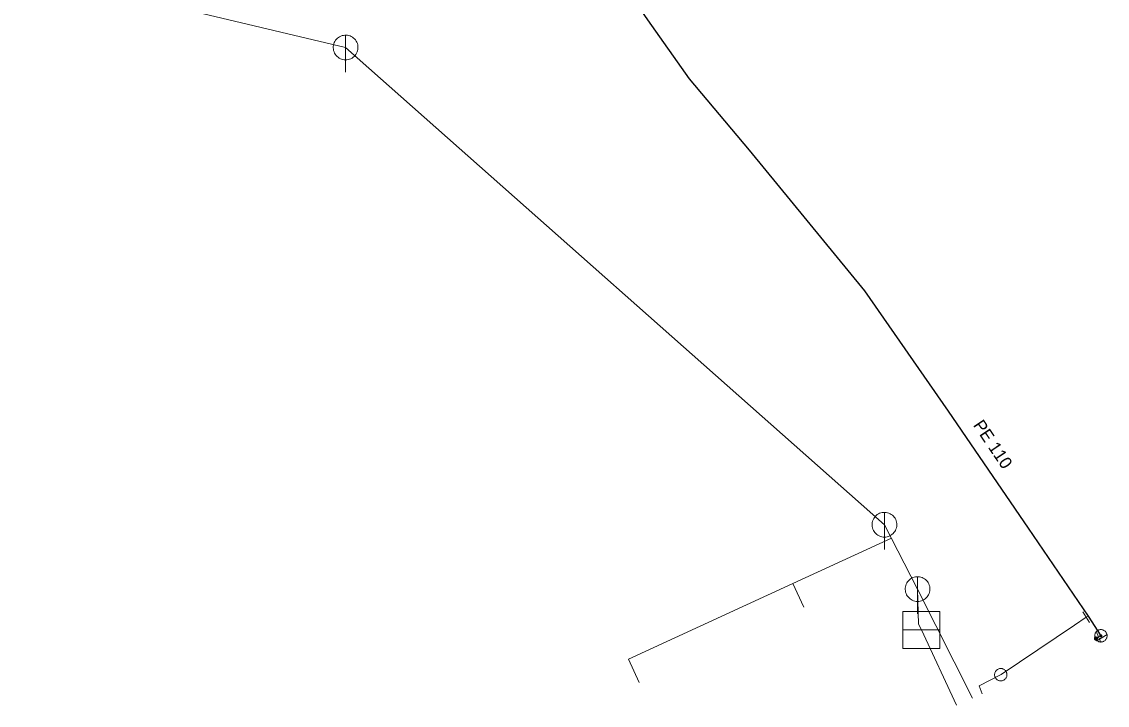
# Model space of a CAD drawing. Extents: x -659250 to -657316, y -997555 to -993684.
# Drawn here: x -658094.3 to -658006.5, y -996520.5 to -996465.3 of the extents above; entities that cross this region are included whole.
import ezdxf

# ---------------------------------------------------------------- set-up
doc = ezdxf.new("R2010")
doc.units = 0
doc.header["$LTSCALE"] = 0.4
doc.layers.add('1', color=7, linetype='Continuous')
for name, color, linetype, lineweight in [('11', 7, 'Continuous', 13), ('13', 7, 'Continuous', 13), ('14', 7, 'Continuous', 25), ('17', 7, 'Continuous', 25), ('22', 7, 'Continuous', 13), ('23', 7, 'Continuous', 13), ('34', 7, 'Continuous', 13), ('47', 7, 'Continuous', 13), ('9', 7, 'Continuous', 13)]:
    doc.layers.add(name, color=color, linetype=linetype, lineweight=lineweight)

msp = doc.modelspace()

# ---------------------------------------------------------------- linework, layer by layer
at = {"layer": '11'}
for p, q in [((-658068.112, -996467.351), (-658094.3, -996461.12)), ((-658024.55, -996505.92), (-658068.112, -996467.351)), ((-658021.87, -996511.12), (-658024.55, -996505.92)), ((-658031.061, -996512.596), (-658031.954, -996510.66)), ((-658017.443, -996519.932), (-658021.87, -996511.12)), ((-658018.721, -996520.515), (-658021.559, -996514.43))]:
    msp.add_line(p, q, dxfattribs=at)
for points in [[(-658044.375, -996518.677), (-658045.245, -996516.787), (-658031.954, -996510.66), (-658023.992, -996507)], [(-658021.559, -996514.43), (-658021.789, -996513.969), (-658021.87, -996511.12)]]:
    msp.add_lwpolyline(points, dxfattribs=at)
at = {"layer": '13'}
for points in [[(-658008.239, -996513.399), (-658009.18, -996514.05), (-658015.12, -996518.02)], [(-658015.12, -996518.02), (-658016.879, -996518.93), (-658016.64, -996519.579)]]:
    msp.add_lwpolyline(points, dxfattribs=at)
at = {"layer": '14', "lineweight": 13}
for p, q in [((-658008.079, -996513.3), (-658008.239, -996513.399)), ((-658007.25, -996514.98), (-658007.449, -996515.12)), ((-658007.05, -996514.899), (-658007.25, -996514.98))]:
    msp.add_line(p, q, dxfattribs=at)
at = {"layer": '17'}
msp.add_line((-658007.05, -996514.899), (-658006.96, -996515.05), dxfattribs=at)
msp.add_lwpolyline([(-658055.539, -996447.693), (-658052.98, -996451.609), (-658043.719, -996465.109), (-658040.35, -996469.87), (-658035.489, -996475.649), (-658026.16, -996487.01), (-658019.39, -996496.739), (-658012.93, -996506.21), (-658008.079, -996513.3), (-658007.05, -996514.899)], dxfattribs=at)
at = {"layer": '22'}
for p, q in [((-658068.112, -996469.351), (-658068.111, -996466.351)), ((-658024.55, -996507.92), (-658024.549, -996504.92)), ((-658021.87, -996513.12), (-658021.869, -996510.12)), ((-658023.059, -996514.43), (-658020.059, -996514.43))]:
    msp.add_line(p, q, dxfattribs=at)
for points in [[(-658067.112, -996467.351), (-658067.117, -996467.242), (-658067.135, -996467.134), (-658067.165, -996467.028), (-658067.205, -996466.927), (-658067.257, -996466.83), (-658067.319, -996466.74), (-658067.391, -996466.657), (-658067.471, -996466.583), (-658067.559, -996466.517), (-658067.653, -996466.462), (-658067.753, -996466.417), (-658067.858, -996466.384), (-658067.965, -996466.362), (-658068.074, -996466.352), (-658068.184, -996466.354), (-658068.292, -996466.368), (-658068.399, -996466.393), (-658068.502, -996466.43), (-658068.6, -996466.479), (-658068.692, -996466.537), (-658068.778, -996466.606), (-658068.855, -996466.683), (-658068.924, -996466.769), (-658068.983, -996466.861), (-658069.031, -996466.959), (-658069.068, -996467.062), (-658069.094, -996467.169), (-658069.108, -996467.277), (-658069.111, -996467.387), (-658069.101, -996467.496), (-658069.08, -996467.603), (-658069.046, -996467.707), (-658069.002, -996467.807), (-658068.947, -996467.902), (-658068.881, -996467.99), (-658068.807, -996468.07), (-658068.724, -996468.142), (-658068.634, -996468.204), (-658068.538, -996468.256), (-658068.436, -996468.297), (-658068.331, -996468.327), (-658068.223, -996468.345), (-658068.113, -996468.351), (-658068.004, -996468.345), (-658067.896, -996468.327), (-658067.791, -996468.298), (-658067.689, -996468.257), (-658067.592, -996468.205), (-658067.502, -996468.143), (-658067.419, -996468.072), (-658067.344, -996467.992), (-658067.279, -996467.904), (-658067.223, -996467.81), (-658067.179, -996467.71), (-658067.145, -996467.606), (-658067.123, -996467.498), (-658067.113, -996467.389)], [(-658023.55, -996505.92), (-658023.555, -996505.811), (-658023.573, -996505.703), (-658023.603, -996505.597), (-658023.643, -996505.496), (-658023.695, -996505.399), (-658023.757, -996505.309), (-658023.829, -996505.226), (-658023.909, -996505.152), (-658023.997, -996505.086), (-658024.091, -996505.031), (-658024.191, -996504.986), (-658024.296, -996504.953), (-658024.403, -996504.931), (-658024.512, -996504.921), (-658024.622, -996504.923), (-658024.73, -996504.937), (-658024.837, -996504.962), (-658024.94, -996504.999), (-658025.038, -996505.048), (-658025.13, -996505.106), (-658025.216, -996505.175), (-658025.293, -996505.252), (-658025.362, -996505.338), (-658025.421, -996505.43), (-658025.469, -996505.528), (-658025.506, -996505.631), (-658025.532, -996505.738), (-658025.546, -996505.846), (-658025.549, -996505.956), (-658025.539, -996506.065), (-658025.518, -996506.172), (-658025.484, -996506.276), (-658025.44, -996506.376), (-658025.385, -996506.471), (-658025.319, -996506.559), (-658025.245, -996506.639), (-658025.162, -996506.711), (-658025.072, -996506.773), (-658024.976, -996506.825), (-658024.874, -996506.866), (-658024.769, -996506.896), (-658024.661, -996506.914), (-658024.551, -996506.92), (-658024.442, -996506.914), (-658024.334, -996506.896), (-658024.229, -996506.867), (-658024.127, -996506.826), (-658024.03, -996506.774), (-658023.94, -996506.712), (-658023.857, -996506.641), (-658023.782, -996506.561), (-658023.717, -996506.473), (-658023.661, -996506.379), (-658023.617, -996506.279), (-658023.583, -996506.175), (-658023.561, -996506.067), (-658023.551, -996505.958)], [(-658020.87, -996511.12), (-658020.875, -996511.011), (-658020.893, -996510.903), (-658020.923, -996510.797), (-658020.963, -996510.696), (-658021.015, -996510.599), (-658021.077, -996510.509), (-658021.149, -996510.426), (-658021.229, -996510.352), (-658021.317, -996510.286), (-658021.411, -996510.231), (-658021.511, -996510.186), (-658021.616, -996510.153), (-658021.723, -996510.131), (-658021.832, -996510.121), (-658021.942, -996510.123), (-658022.05, -996510.137), (-658022.157, -996510.162), (-658022.26, -996510.199), (-658022.358, -996510.248), (-658022.45, -996510.306), (-658022.536, -996510.375), (-658022.613, -996510.452), (-658022.682, -996510.538), (-658022.741, -996510.63), (-658022.789, -996510.728), (-658022.826, -996510.831), (-658022.852, -996510.938), (-658022.866, -996511.046), (-658022.869, -996511.156), (-658022.859, -996511.265), (-658022.838, -996511.372), (-658022.804, -996511.476), (-658022.76, -996511.576), (-658022.705, -996511.671), (-658022.639, -996511.759), (-658022.565, -996511.839), (-658022.482, -996511.911), (-658022.392, -996511.973), (-658022.296, -996512.025), (-658022.194, -996512.066), (-658022.089, -996512.096), (-658021.981, -996512.114), (-658021.871, -996512.12), (-658021.762, -996512.114), (-658021.654, -996512.096), (-658021.549, -996512.067), (-658021.447, -996512.026), (-658021.35, -996511.974), (-658021.26, -996511.912), (-658021.177, -996511.841), (-658021.102, -996511.761), (-658021.037, -996511.673), (-658020.981, -996511.579), (-658020.937, -996511.479), (-658020.903, -996511.375), (-658020.881, -996511.267), (-658020.871, -996511.158)], [(-658023.059, -996512.93), (-658020.059, -996512.93), (-658020.059, -996515.93), (-658023.059, -996515.93)]]:
    msp.add_lwpolyline(points, close=True, dxfattribs=at)
at = {"layer": '23'}
for points in [[(-658014.643, -996518.037), (-658014.646, -996517.984), (-658014.655, -996517.932), (-658014.67, -996517.883), (-658014.689, -996517.834), (-658014.713, -996517.788), (-658014.743, -996517.744), (-658014.776, -996517.704), (-658014.813, -996517.668), (-658014.854, -996517.635), (-658014.898, -996517.607), (-658014.945, -996517.583), (-658014.995, -996517.565), (-658015.045, -996517.552), (-658015.096, -996517.545), (-658015.148, -996517.542), (-658015.202, -996517.546), (-658015.252, -996517.554), (-658015.304, -996517.569), (-658015.351, -996517.587), (-658015.398, -996517.611), (-658015.442, -996517.642), (-658015.482, -996517.675), (-658015.519, -996517.713), (-658015.552, -996517.753), (-658015.579, -996517.797), (-658015.602, -996517.845), (-658015.62, -996517.893), (-658015.633, -996517.944), (-658015.64, -996517.996), (-658015.643, -996518.048), (-658015.64, -996518.1), (-658015.631, -996518.152), (-658015.617, -996518.203), (-658015.598, -996518.251), (-658015.573, -996518.296), (-658015.544, -996518.34), (-658015.511, -996518.381), (-658015.473, -996518.418), (-658015.432, -996518.45)], [(-658015.304, -996517.569), (-658015.351, -996517.587), (-658015.398, -996517.611), (-658015.442, -996517.642), (-658015.482, -996517.675), (-658015.519, -996517.713), (-658015.552, -996517.753), (-658015.579, -996517.797), (-658015.602, -996517.845), (-658015.62, -996517.893), (-658015.633, -996517.944), (-658015.64, -996517.996), (-658015.643, -996518.048), (-658015.64, -996518.1), (-658015.631, -996518.152), (-658015.617, -996518.203), (-658015.598, -996518.251), (-658015.573, -996518.296), (-658015.544, -996518.34), (-658015.511, -996518.381), (-658015.473, -996518.418), (-658015.432, -996518.45), (-658015.389, -996518.478), (-658015.341, -996518.501), (-658015.293, -996518.52), (-658015.241, -996518.532), (-658015.19, -996518.539), (-658015.138, -996518.542), (-658015.086, -996518.538), (-658015.034, -996518.53), (-658014.983, -996518.516), (-658014.934, -996518.496), (-658014.888, -996518.472), (-658014.845, -996518.444), (-658014.805, -996518.409), (-658014.768, -996518.373), (-658014.736, -996518.332), (-658014.707, -996518.287), (-658014.684, -996518.24), (-658014.666, -996518.191)], [(-658015.432, -996518.45), (-658015.389, -996518.478), (-658015.341, -996518.501), (-658015.293, -996518.52), (-658015.241, -996518.532), (-658015.19, -996518.539), (-658015.138, -996518.542), (-658015.086, -996518.538), (-658015.034, -996518.53), (-658014.983, -996518.516), (-658014.934, -996518.496), (-658014.888, -996518.472), (-658014.845, -996518.444), (-658014.805, -996518.409), (-658014.768, -996518.373), (-658014.736, -996518.332), (-658014.707, -996518.287), (-658014.684, -996518.24), (-658014.666, -996518.191), (-658014.654, -996518.14), (-658014.646, -996518.089), (-658014.643, -996518.037), (-658014.646, -996517.984), (-658014.655, -996517.932), (-658014.67, -996517.883), (-658014.689, -996517.834), (-658014.713, -996517.788), (-658014.743, -996517.744), (-658014.776, -996517.704), (-658014.813, -996517.668), (-658014.854, -996517.635), (-658014.898, -996517.607), (-658014.945, -996517.583), (-658014.995, -996517.565), (-658015.045, -996517.552), (-658015.096, -996517.545), (-658015.148, -996517.542), (-658015.202, -996517.546), (-658015.252, -996517.554), (-658015.304, -996517.569)], [(-658014.666, -996518.191), (-658014.654, -996518.14), (-658014.646, -996518.089), (-658014.643, -996518.037)]]:
    msp.add_lwpolyline(points, dxfattribs=at)
at = {"layer": '34'}
for p, q in [((-658007.973, -996513.822), (-658008.503, -996512.974)), ((-658007.063, -996515.444), (-658007.435, -996514.515))]:
    msp.add_line(p, q, dxfattribs=at)
at = {"layer": '47'}
for points in [[(-658006.55, -996514.899), (-658006.553, -996514.847), (-658006.561, -996514.794), (-658006.575, -996514.745), (-658006.593, -996514.696), (-658006.617, -996514.649), (-658006.646, -996514.605), (-658006.679, -996514.565), (-658006.716, -996514.527), (-658006.756, -996514.495), (-658006.8, -996514.466), (-658006.847, -996514.441), (-658006.896, -996514.424), (-658006.946, -996514.41), (-658006.998, -996514.402), (-658007.05, -996514.399), (-658007.102, -996514.402), (-658007.154, -996514.41), (-658007.205, -996514.424), (-658007.253, -996514.441), (-658007.3, -996514.466), (-658007.344, -996514.495), (-658007.385, -996514.527), (-658007.422, -996514.565), (-658007.455, -996514.605), (-658007.483, -996514.649), (-658007.507, -996514.696), (-658007.526, -996514.745), (-658007.539, -996514.794), (-658007.547, -996514.847), (-658007.55, -996514.899), (-658007.547, -996514.951), (-658007.539, -996515.003), (-658007.526, -996515.054), (-658007.507, -996515.102), (-658007.483, -996515.149), (-658007.455, -996515.193), (-658007.422, -996515.233), (-658007.385, -996515.271), (-658007.344, -996515.304), (-658007.3, -996515.331), (-658007.253, -996515.356), (-658007.205, -996515.375), (-658007.154, -996515.387), (-658007.102, -996515.396), (-658007.05, -996515.399), (-658006.998, -996515.396), (-658006.946, -996515.387), (-658006.896, -996515.375), (-658006.847, -996515.356), (-658006.8, -996515.331), (-658006.756, -996515.304), (-658006.716, -996515.271), (-658006.679, -996515.233), (-658006.646, -996515.193), (-658006.617, -996515.149), (-658006.593, -996515.102), (-658006.575, -996515.054), (-658006.561, -996515.003), (-658006.553, -996514.951)], [(-658006.968, -996514.899), (-658006.968, -996514.89), (-658006.97, -996514.882), (-658006.972, -996514.874), (-658006.975, -996514.865), (-658006.979, -996514.858), (-658006.984, -996514.851), (-658006.989, -996514.843), (-658006.995, -996514.838), (-658007.002, -996514.833), (-658007.009, -996514.828), (-658007.017, -996514.824), (-658007.025, -996514.821), (-658007.033, -996514.819), (-658007.041, -996514.816), (-658007.05, -996514.816), (-658007.059, -996514.816), (-658007.067, -996514.819), (-658007.075, -996514.821), (-658007.083, -996514.824), (-658007.091, -996514.828), (-658007.098, -996514.833), (-658007.105, -996514.838), (-658007.111, -996514.843), (-658007.117, -996514.851), (-658007.121, -996514.858), (-658007.125, -996514.865), (-658007.128, -996514.874), (-658007.13, -996514.882), (-658007.132, -996514.89), (-658007.132, -996514.899), (-658007.132, -996514.907), (-658007.13, -996514.916), (-658007.128, -996514.924), (-658007.125, -996514.932), (-658007.121, -996514.94), (-658007.117, -996514.946), (-658007.111, -996514.954), (-658007.105, -996514.96), (-658007.098, -996514.966), (-658007.091, -996514.97), (-658007.083, -996514.973), (-658007.075, -996514.977), (-658007.067, -996514.978), (-658007.059, -996514.981), (-658007.05, -996514.981), (-658007.041, -996514.981), (-658007.033, -996514.978), (-658007.025, -996514.977), (-658007.017, -996514.973), (-658007.009, -996514.97), (-658007.002, -996514.966), (-658006.995, -996514.96), (-658006.989, -996514.954), (-658006.984, -996514.946), (-658006.979, -996514.94), (-658006.975, -996514.932), (-658006.972, -996514.924), (-658006.97, -996514.916), (-658006.968, -996514.907)]]:
    msp.add_lwpolyline(points, close=True, dxfattribs=at)
msp.add_lwpolyline([(-658006.664, -996514.578), (-658006.534, -996514.794), (-658007.385, -996515.305), (-658007.514, -996515.089)], dxfattribs=at)
at = {"layer": '9'}
for points in [[(-658007.575, -996515.12), (-658007.575, -996515.133), (-658007.573, -996515.146), (-658007.57, -996515.159), (-658007.565, -996515.171), (-658007.559, -996515.183), (-658007.552, -996515.194), (-658007.544, -996515.204), (-658007.534, -996515.214), (-658007.524, -996515.222), (-658007.513, -996515.229), (-658007.501, -996515.235), (-658007.489, -996515.24), (-658007.476, -996515.243), (-658007.463, -996515.245), (-658007.45, -996515.247), (-658007.437, -996515.246), (-658007.424, -996515.244), (-658007.411, -996515.241), (-658007.399, -996515.236), (-658007.387, -996515.23), (-658007.376, -996515.223), (-658007.366, -996515.215), (-658007.356, -996515.205), (-658007.348, -996515.195), (-658007.341, -996515.184), (-658007.335, -996515.172), (-658007.33, -996515.16), (-658007.327, -996515.147), (-658007.325, -996515.134), (-658007.323, -996515.121), (-658007.324, -996515.108), (-658007.326, -996515.095), (-658007.329, -996515.082), (-658007.334, -996515.07), (-658007.34, -996515.058), (-658007.347, -996515.047), (-658007.355, -996515.037), (-658007.365, -996515.027), (-658007.375, -996515.019), (-658007.386, -996515.012), (-658007.398, -996515.006), (-658007.41, -996515.001), (-658007.423, -996514.998), (-658007.436, -996514.996), (-658007.449, -996514.995), (-658007.462, -996514.995), (-658007.475, -996514.997), (-658007.488, -996515), (-658007.5, -996515.005), (-658007.512, -996515.011), (-658007.523, -996515.018), (-658007.533, -996515.026), (-658007.543, -996515.036), (-658007.551, -996515.046), (-658007.558, -996515.057), (-658007.564, -996515.069), (-658007.569, -996515.081), (-658007.572, -996515.094), (-658007.574, -996515.107)], [(-658007.555, -996515.12), (-658007.556, -996515.131), (-658007.554, -996515.142), (-658007.551, -996515.153), (-658007.547, -996515.163), (-658007.542, -996515.173), (-658007.536, -996515.182), (-658007.529, -996515.191), (-658007.521, -996515.199), (-658007.512, -996515.206), (-658007.503, -996515.212), (-658007.493, -996515.217), (-658007.483, -996515.221), (-658007.472, -996515.224), (-658007.461, -996515.227), (-658007.45, -996515.227), (-658007.439, -996515.227), (-658007.428, -996515.225), (-658007.417, -996515.222), (-658007.407, -996515.218), (-658007.397, -996515.213), (-658007.388, -996515.207), (-658007.379, -996515.2), (-658007.371, -996515.192), (-658007.364, -996515.183), (-658007.358, -996515.174), (-658007.353, -996515.164), (-658007.349, -996515.154), (-658007.346, -996515.143), (-658007.344, -996515.132), (-658007.343, -996515.121), (-658007.343, -996515.11), (-658007.345, -996515.099), (-658007.348, -996515.088), (-658007.352, -996515.078), (-658007.357, -996515.068), (-658007.363, -996515.059), (-658007.37, -996515.05), (-658007.378, -996515.042), (-658007.387, -996515.035), (-658007.396, -996515.029), (-658007.406, -996515.024), (-658007.416, -996515.02), (-658007.427, -996515.017), (-658007.438, -996515.015), (-658007.449, -996515.015), (-658007.46, -996515.014), (-658007.471, -996515.016), (-658007.482, -996515.019), (-658007.492, -996515.023), (-658007.502, -996515.028), (-658007.511, -996515.034), (-658007.52, -996515.041), (-658007.528, -996515.049), (-658007.535, -996515.058), (-658007.541, -996515.067), (-658007.546, -996515.077), (-658007.55, -996515.087), (-658007.553, -996515.098), (-658007.555, -996515.109)], [(-658007.536, -996515.12), (-658007.536, -996515.129), (-658007.535, -996515.138), (-658007.532, -996515.147), (-658007.529, -996515.155), (-658007.525, -996515.163), (-658007.52, -996515.171), (-658007.514, -996515.178), (-658007.508, -996515.184), (-658007.501, -996515.19), (-658007.493, -996515.195), (-658007.485, -996515.199), (-658007.477, -996515.202), (-658007.468, -996515.205), (-658007.459, -996515.206), (-658007.45, -996515.208), (-658007.441, -996515.207), (-658007.432, -996515.206), (-658007.423, -996515.203), (-658007.415, -996515.2), (-658007.407, -996515.196), (-658007.399, -996515.191), (-658007.392, -996515.185), (-658007.386, -996515.179), (-658007.38, -996515.172), (-658007.375, -996515.164), (-658007.371, -996515.156), (-658007.368, -996515.148), (-658007.365, -996515.139), (-658007.364, -996515.13), (-658007.362, -996515.121), (-658007.363, -996515.112), (-658007.364, -996515.103), (-658007.367, -996515.094), (-658007.37, -996515.086), (-658007.374, -996515.078), (-658007.379, -996515.07), (-658007.385, -996515.063), (-658007.391, -996515.057), (-658007.398, -996515.051), (-658007.406, -996515.046), (-658007.414, -996515.042), (-658007.422, -996515.039), (-658007.431, -996515.036), (-658007.44, -996515.035), (-658007.449, -996515.034), (-658007.458, -996515.034), (-658007.467, -996515.035), (-658007.476, -996515.038), (-658007.484, -996515.041), (-658007.492, -996515.045), (-658007.5, -996515.05), (-658007.507, -996515.056), (-658007.513, -996515.062), (-658007.519, -996515.069), (-658007.524, -996515.077), (-658007.528, -996515.085), (-658007.531, -996515.093), (-658007.534, -996515.102), (-658007.535, -996515.111)], [(-658007.516, -996515.12), (-658007.516, -996515.127), (-658007.515, -996515.134), (-658007.514, -996515.141), (-658007.511, -996515.147), (-658007.508, -996515.153), (-658007.504, -996515.159), (-658007.5, -996515.165), (-658007.495, -996515.17), (-658007.489, -996515.174), (-658007.483, -996515.178), (-658007.477, -996515.181), (-658007.471, -996515.184), (-658007.464, -996515.185), (-658007.457, -996515.188), (-658007.45, -996515.188), (-658007.443, -996515.188), (-658007.436, -996515.186), (-658007.429, -996515.185), (-658007.423, -996515.182), (-658007.416, -996515.179), (-658007.411, -996515.175), (-658007.405, -996515.171), (-658007.4, -996515.166), (-658007.396, -996515.16), (-658007.392, -996515.154), (-658007.389, -996515.148), (-658007.386, -996515.142), (-658007.384, -996515.135), (-658007.383, -996515.128), (-658007.382, -996515.121), (-658007.382, -996515.114), (-658007.383, -996515.107), (-658007.385, -996515.1), (-658007.388, -996515.094), (-658007.391, -996515.087), (-658007.395, -996515.082), (-658007.399, -996515.076), (-658007.404, -996515.071), (-658007.41, -996515.067), (-658007.415, -996515.063), (-658007.422, -996515.06), (-658007.428, -996515.057), (-658007.435, -996515.055), (-658007.442, -996515.054), (-658007.449, -996515.054), (-658007.456, -996515.054), (-658007.463, -996515.054), (-658007.47, -996515.056), (-658007.476, -996515.059), (-658007.482, -996515.062), (-658007.488, -996515.066), (-658007.494, -996515.07), (-658007.499, -996515.075), (-658007.503, -996515.081), (-658007.507, -996515.086), (-658007.51, -996515.093), (-658007.513, -996515.099), (-658007.514, -996515.106), (-658007.516, -996515.113)], [(-658007.496, -996515.12), (-658007.496, -996515.125), (-658007.496, -996515.13), (-658007.495, -996515.135), (-658007.493, -996515.139), (-658007.491, -996515.144), (-658007.488, -996515.148), (-658007.485, -996515.151), (-658007.481, -996515.155), (-658007.478, -996515.158), (-658007.474, -996515.161), (-658007.469, -996515.163), (-658007.465, -996515.165), (-658007.46, -996515.166), (-658007.455, -996515.168), (-658007.45, -996515.168), (-658007.445, -996515.168), (-658007.44, -996515.167), (-658007.435, -996515.166), (-658007.431, -996515.164), (-658007.426, -996515.162), (-658007.422, -996515.159), (-658007.418, -996515.156), (-658007.415, -996515.152), (-658007.412, -996515.149), (-658007.409, -996515.145), (-658007.407, -996515.14), (-658007.405, -996515.136), (-658007.404, -996515.131), (-658007.403, -996515.126), (-658007.402, -996515.121), (-658007.402, -996515.116), (-658007.403, -996515.111), (-658007.404, -996515.106), (-658007.406, -996515.102), (-658007.408, -996515.097), (-658007.411, -996515.093), (-658007.414, -996515.089), (-658007.417, -996515.086), (-658007.421, -996515.083), (-658007.425, -996515.08), (-658007.43, -996515.078), (-658007.434, -996515.076), (-658007.439, -996515.075), (-658007.444, -996515.074), (-658007.449, -996515.074), (-658007.454, -996515.074), (-658007.459, -996515.075), (-658007.464, -996515.075), (-658007.468, -996515.077), (-658007.473, -996515.079), (-658007.477, -996515.082), (-658007.48, -996515.085), (-658007.484, -996515.088), (-658007.487, -996515.092), (-658007.49, -996515.096), (-658007.492, -996515.101), (-658007.494, -996515.105), (-658007.495, -996515.11), (-658007.496, -996515.115)], [(-658007.476, -996515.12), (-658007.476, -996515.123), (-658007.477, -996515.126), (-658007.476, -996515.128), (-658007.475, -996515.131), (-658007.474, -996515.134), (-658007.472, -996515.136), (-658007.47, -996515.138), (-658007.468, -996515.14), (-658007.466, -996515.142), (-658007.464, -996515.144), (-658007.461, -996515.146), (-658007.458, -996515.147), (-658007.456, -996515.147), (-658007.453, -996515.148), (-658007.45, -996515.148), (-658007.447, -996515.148), (-658007.444, -996515.148), (-658007.441, -996515.147), (-658007.439, -996515.146), (-658007.436, -996515.145), (-658007.434, -996515.143), (-658007.431, -996515.141), (-658007.429, -996515.139), (-658007.428, -996515.137), (-658007.426, -996515.135), (-658007.425, -996515.132), (-658007.423, -996515.129), (-658007.423, -996515.127), (-658007.422, -996515.124), (-658007.421, -996515.121), (-658007.422, -996515.118), (-658007.422, -996515.115), (-658007.423, -996515.112), (-658007.424, -996515.11), (-658007.425, -996515.107), (-658007.427, -996515.105), (-658007.428, -996515.102), (-658007.43, -996515.1), (-658007.433, -996515.099), (-658007.435, -996515.097), (-658007.438, -996515.096), (-658007.44, -996515.095), (-658007.443, -996515.094), (-658007.446, -996515.094), (-658007.449, -996515.093), (-658007.452, -996515.094), (-658007.455, -996515.093), (-658007.457, -996515.095), (-658007.46, -996515.095), (-658007.463, -996515.096), (-658007.465, -996515.098), (-658007.467, -996515.099), (-658007.469, -996515.101), (-658007.471, -996515.104), (-658007.473, -996515.106), (-658007.474, -996515.109), (-658007.475, -996515.111), (-658007.476, -996515.114), (-658007.476, -996515.117)], [(-658007.457, -996515.12), (-658007.457, -996515.122), (-658007.457, -996515.122), (-658007.456, -996515.122), (-658007.456, -996515.124), (-658007.457, -996515.125), (-658007.455, -996515.125), (-658007.455, -996515.125), (-658007.455, -996515.127), (-658007.455, -996515.127), (-658007.454, -996515.128), (-658007.452, -996515.128), (-658007.452, -996515.128), (-658007.452, -996515.129), (-658007.45, -996515.129), (-658007.45, -996515.129), (-658007.449, -996515.129), (-658007.448, -996515.129), (-658007.448, -996515.128), (-658007.447, -996515.128), (-658007.445, -996515.128), (-658007.445, -996515.127), (-658007.445, -996515.127), (-658007.444, -996515.126), (-658007.444, -996515.126), (-658007.442, -996515.125), (-658007.442, -996515.124), (-658007.441, -996515.123), (-658007.441, -996515.123), (-658007.441, -996515.122), (-658007.441, -996515.121), (-658007.441, -996515.12), (-658007.441, -996515.119), (-658007.441, -996515.119), (-658007.442, -996515.118), (-658007.442, -996515.117), (-658007.443, -996515.116), (-658007.443, -996515.116), (-658007.444, -996515.115), (-658007.444, -996515.115), (-658007.445, -996515.114), (-658007.446, -996515.114), (-658007.447, -996515.113), (-658007.447, -996515.113), (-658007.448, -996515.113), (-658007.449, -996515.113), (-658007.45, -996515.113), (-658007.451, -996515.113), (-658007.451, -996515.113), (-658007.452, -996515.114), (-658007.453, -996515.113), (-658007.454, -996515.115), (-658007.454, -996515.115), (-658007.455, -996515.115), (-658007.455, -996515.115), (-658007.456, -996515.117), (-658007.456, -996515.118), (-658007.456, -996515.119), (-658007.457, -996515.119), (-658007.457, -996515.12)]]:
    msp.add_lwpolyline(points, close=True, dxfattribs=at)

# ---------------------------------------------------------------- texts
at = {"layer": '1'}
msp.add_text('PE 110', height=1, rotation=304, dxfattribs=at).set_placement((-658017.417, -996497.874))

doc.saveas('drawing.dxf')
